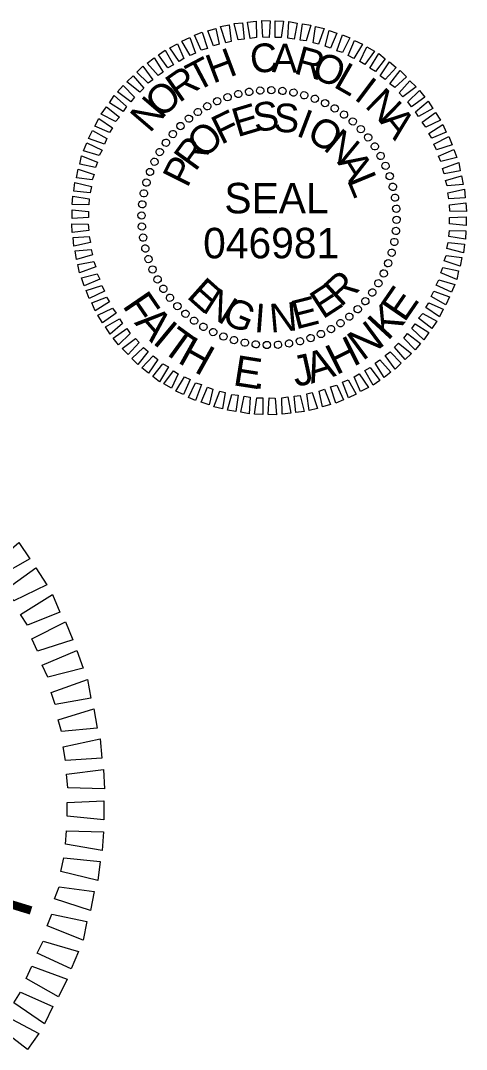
# Model space of a CAD drawing. Extents: x 1184048.9 to 1184122, y 1246638.9 to 1246660.6.
# Drawn here: x 1184120.43 to 1184122.001, y 1246653.225 to 1246656.855 of the extents above; entities that cross this region are included whole.
import ezdxf

# ---------------------------------------------------------------- set-up
doc = ezdxf.new("R2010")
doc.units = 0
doc.layers.add('Sheet PE Seal CELL', color=7, linetype='Continuous')

msp = doc.modelspace()

# ---------------------------------------------------------------- linework, layer by layer
at = {"layer": 'Sheet PE Seal CELL'}
for p, q in [((1184121.1588, 1246656.585), (1184121.1588, 1246656.585)), ((1184121.1964, 1246656.5958), (1184121.1964, 1246656.5958)), ((1184121.2359, 1246656.6029), (1184121.2359, 1246656.6029)), ((1184121.2744, 1246656.6083), (1184121.2744, 1246656.6083)), ((1184121.3138, 1246656.6092), (1184121.3138, 1246656.6092)), ((1184121.3532, 1246656.6065), (1184121.3532, 1246656.6065)), ((1184121.3917, 1246656.6003), (1184121.3917, 1246656.6003)), ((1184121.4293, 1246656.5922), (1184121.4293, 1246656.5922)), ((1184121.467, 1246656.5796), (1184121.467, 1246656.5796)), ((1184121.088, 1246656.5528), (1184121.088, 1246656.5528)), ((1184121.123, 1246656.5707), (1184121.123, 1246656.5707)), ((1184121.5028, 1246656.5635), (1184121.5028, 1246656.5635)), ((1184121.5377, 1246656.5456), (1184121.5377, 1246656.5456)), ((1184121.0227, 1246656.5098), (1184121.0227, 1246656.5098)), ((1184121.054, 1246656.5322), (1184121.054, 1246656.5322)), ((1184121.57, 1246656.5232), (1184121.57, 1246656.5232)), ((1184120.9931, 1246656.4829), (1184120.9931, 1246656.4829)), ((1184121.6013, 1246656.499), (1184121.6013, 1246656.499)), ((1184121.6291, 1246656.4722), (1184121.6291, 1246656.4722)), ((1184120.9662, 1246656.4551), (1184120.9662, 1246656.4551)), ((1184121.656, 1246656.4426), (1184121.656, 1246656.4426)), ((1184120.942, 1246656.4238), (1184120.942, 1246656.4238)), ((1184121.6784, 1246656.4112), (1184121.6784, 1246656.4112)), ((1184120.9196, 1246656.3915), (1184120.9196, 1246656.3915)), ((1184121.699, 1246656.3772), (1184121.699, 1246656.3772)), ((1184120.9017, 1246656.3566), (1184120.9017, 1246656.3566)), ((1184121.7169, 1246656.3423), (1184121.7169, 1246656.3423)), ((1184120.8856, 1246656.3208), (1184120.8856, 1246656.3208)), ((1184121.7312, 1246656.3064), (1184121.7312, 1246656.3064)), ((1184120.8731, 1246656.2831), (1184120.8731, 1246656.2831)), ((1184121.742, 1246656.2688), (1184121.742, 1246656.2688)), ((1184120.865, 1246656.2455), (1184120.865, 1246656.2455)), ((1184121.7491, 1246656.2294), (1184121.7491, 1246656.2294)), ((1184120.8587, 1246656.207), (1184120.8587, 1246656.207)), ((1184121.7545, 1246656.1909), (1184121.7545, 1246656.1909)), ((1184120.856, 1246656.1676), (1184120.856, 1246656.1676)), ((1184121.3057, 1246656.1595), (1184121.3057, 1246656.1595)), ((1184121.7554, 1246656.1515), (1184121.7554, 1246656.1515)), ((1184120.8569, 1246656.1282), (1184120.8569, 1246656.1282)), ((1184121.7527, 1246656.1121), (1184121.7527, 1246656.1121)), ((1184120.8623, 1246656.0897), (1184120.8623, 1246656.0897)), ((1184121.7464, 1246656.0735), (1184121.7464, 1246656.0735)), ((1184120.8695, 1246656.0502), (1184120.8695, 1246656.0502)), ((1184121.7384, 1246656.0359), (1184121.7384, 1246656.0359)), ((1184120.8802, 1246656.0126), (1184120.8802, 1246656.0126)), ((1184121.7258, 1246655.9983), (1184121.7258, 1246655.9983)), ((1184120.8946, 1246655.9768), (1184120.8946, 1246655.9768)), ((1184121.7097, 1246655.9625), (1184121.7097, 1246655.9625)), ((1184120.9125, 1246655.9419), (1184120.9125, 1246655.9419)), ((1184121.6918, 1246655.9275), (1184121.6918, 1246655.9275)), ((1184120.9331, 1246655.9078), (1184120.9331, 1246655.9078)), ((1184121.6694, 1246655.8953), (1184121.6694, 1246655.8953)), ((1184120.9555, 1246655.8765), (1184120.9555, 1246655.8765)), ((1184121.6452, 1246655.8639), (1184121.6452, 1246655.8639)), ((1184120.9823, 1246655.8469), (1184120.9823, 1246655.8469)), ((1184121.0101, 1246655.82), (1184121.0101, 1246655.82)), ((1184121.6183, 1246655.8362), (1184121.6183, 1246655.8362)), ((1184121.0415, 1246655.7958), (1184121.0415, 1246655.7958)), ((1184121.5574, 1246655.7869), (1184121.5574, 1246655.7869)), ((1184121.5888, 1246655.8093), (1184121.5888, 1246655.8093)), ((1184121.0737, 1246655.7735), (1184121.0737, 1246655.7735)), ((1184121.1087, 1246655.7555), (1184121.1087, 1246655.7555)), ((1184121.4885, 1246655.7484), (1184121.4885, 1246655.7484)), ((1184121.5234, 1246655.7663), (1184121.5234, 1246655.7663)), ((1184121.1445, 1246655.7394), (1184121.1445, 1246655.7394)), ((1184121.1821, 1246655.7269), (1184121.1821, 1246655.7269)), ((1184121.2197, 1246655.7188), (1184121.2197, 1246655.7188)), ((1184121.2582, 1246655.7125), (1184121.2582, 1246655.7125)), ((1184121.2977, 1246655.7099), (1184121.2977, 1246655.7099)), ((1184121.3371, 1246655.7107), (1184121.3371, 1246655.7107)), ((1184121.3756, 1246655.7161), (1184121.3756, 1246655.7161)), ((1184121.415, 1246655.7233), (1184121.415, 1246655.7233)), ((1184121.4526, 1246655.734), (1184121.4526, 1246655.734))]:
    msp.add_line(p, q, dxfattribs=at)
for points in [[(1184121.1534, 1246656.7767), (1184121.1346, 1246656.8332), (1184121.1651, 1246656.8394), (1184121.1723, 1246656.7812)], [(1184121.1964, 1246656.7866), (1184121.1821, 1246656.8439), (1184121.2117, 1246656.8466), (1184121.2179, 1246656.7893)], [(1184121.2394, 1246656.7919), (1184121.2296, 1246656.8493), (1184121.26, 1246656.8529), (1184121.2609, 1246656.7946)], [(1184121.2842, 1246656.7964), (1184121.2797, 1246656.8547), (1184121.3093, 1246656.8538), (1184121.3057, 1246656.7955)], [(1184121.3272, 1246656.7955), (1184121.3272, 1246656.8538), (1184121.3568, 1246656.8529), (1184121.3487, 1246656.7946)], [(1184121.372, 1246656.7928), (1184121.3756, 1246656.8511), (1184121.4052, 1246656.8457), (1184121.3935, 1246656.7893)], [(1184121.415, 1246656.7857), (1184121.4231, 1246656.843), (1184121.4526, 1246656.8385), (1184121.4365, 1246656.783)], [(1184121.4607, 1246656.7758), (1184121.4696, 1246656.834), (1184121.5001, 1246656.8269), (1184121.4795, 1246656.7713)], [(1184121.0666, 1246656.7507), (1184121.0433, 1246656.8027), (1184121.0701, 1246656.8134), (1184121.0889, 1246656.7561)], [(1184121.1104, 1246656.7651), (1184121.0898, 1246656.8188), (1184121.1176, 1246656.8269), (1184121.1293, 1246656.7713)], [(1184121.5037, 1246656.7642), (1184121.5171, 1246656.8197), (1184121.5449, 1246656.8108), (1184121.5225, 1246656.7579)], [(1184121.544, 1246656.7481), (1184121.5646, 1246656.8045), (1184121.5897, 1246656.7937), (1184121.5646, 1246656.7418)], [(1184120.9886, 1246656.7104), (1184120.9555, 1246656.7588), (1184120.9832, 1246656.7731), (1184121.0056, 1246656.7212)], [(1184121.0271, 1246656.7319), (1184120.9985, 1246656.7821), (1184121.0262, 1246656.7946), (1184121.0468, 1246656.74)], [(1184121.5843, 1246656.731), (1184121.6067, 1246656.7839), (1184121.6345, 1246656.7713), (1184121.604, 1246656.7212)], [(1184121.6255, 1246656.7104), (1184121.6497, 1246656.7615), (1184121.6766, 1246656.7463), (1184121.6425, 1246656.6997)], [(1184120.9492, 1246656.688), (1184120.9161, 1246656.7337), (1184120.9394, 1246656.7507), (1184120.9689, 1246656.6988)], [(1184121.6604, 1246656.6862), (1184121.6918, 1246656.7382), (1184121.7151, 1246656.7194), (1184121.6802, 1246656.6755)], [(1184120.8793, 1246656.6334), (1184120.8399, 1246656.6728), (1184120.8614, 1246656.6943), (1184120.8964, 1246656.6459)], [(1184120.9152, 1246656.6612), (1184120.8766, 1246656.7042), (1184120.9008, 1246656.723), (1184120.9322, 1246656.6728)], [(1184121.6972, 1246656.6594), (1184121.7303, 1246656.7086), (1184121.7536, 1246656.6889), (1184121.7142, 1246656.6468)], [(1184120.8498, 1246656.602), (1184120.8041, 1246656.6388), (1184120.8265, 1246656.6594), (1184120.8641, 1246656.6164)], [(1184121.7312, 1246656.6316), (1184121.7679, 1246656.6782), (1184121.7894, 1246656.6567), (1184121.7482, 1246656.6182)], [(1184120.8184, 1246656.568), (1184120.7718, 1246656.6029), (1184120.7915, 1246656.6262), (1184120.831, 1246656.5841)], [(1184121.7635, 1246656.6003), (1184121.802, 1246656.6424), (1184121.8235, 1246656.6209), (1184121.7769, 1246656.5859)], [(1184120.7915, 1246656.534), (1184120.7432, 1246656.5644), (1184120.7602, 1246656.5904), (1184120.8032, 1246656.551)], [(1184121.7948, 1246656.568), (1184121.836, 1246656.6083), (1184121.8548, 1246656.5841), (1184121.8074, 1246656.5501)], [(1184120.7647, 1246656.4981), (1184120.7145, 1246656.525), (1184120.7324, 1246656.5501), (1184120.779, 1246656.5143)], [(1184121.8217, 1246656.5331), (1184121.8656, 1246656.5707), (1184121.8826, 1246656.5447), (1184121.8324, 1246656.516)], [(1184120.7432, 1246656.4596), (1184120.6921, 1246656.482), (1184120.7056, 1246656.5098), (1184120.7539, 1246656.4766)], [(1184121.845, 1246656.4963), (1184121.8925, 1246656.5304), (1184121.9095, 1246656.5035), (1184121.8575, 1246656.4784)], [(1184121.8683, 1246656.4569), (1184121.9184, 1246656.4883), (1184121.9301, 1246656.4605), (1184121.879, 1246656.4399)], [(1184120.7253, 1246656.4184), (1184120.6697, 1246656.439), (1184120.6832, 1246656.4668), (1184120.7342, 1246656.4381)], [(1184121.8862, 1246656.4184), (1184121.939, 1246656.4453), (1184121.9507, 1246656.4166), (1184121.8951, 1246656.3987)], [(1184120.7073, 1246656.379), (1184120.6518, 1246656.3951), (1184120.6635, 1246656.4229), (1184120.7172, 1246656.3978)], [(1184121.9023, 1246656.3763), (1184121.9569, 1246656.3996), (1184121.9668, 1246656.3718), (1184121.9113, 1246656.3575)], [(1184120.6939, 1246656.336), (1184120.6384, 1246656.3476), (1184120.6446, 1246656.3772), (1184120.7011, 1246656.3548)], [(1184120.6823, 1246656.293), (1184120.6267, 1246656.3002), (1184120.633, 1246656.3306), (1184120.6894, 1246656.3118)], [(1184121.9166, 1246656.3333), (1184121.974, 1246656.3539), (1184121.9793, 1246656.3244), (1184121.9229, 1246656.3145)], [(1184121.9274, 1246656.2903), (1184121.9838, 1246656.3073), (1184121.9892, 1246656.2769), (1184121.9328, 1246656.2715)], [(1184120.6751, 1246656.2473), (1184120.6178, 1246656.2527), (1184120.6214, 1246656.2831), (1184120.6796, 1246656.2688)], [(1184121.9355, 1246656.2473), (1184121.9937, 1246656.2599), (1184121.9964, 1246656.2294), (1184121.939, 1246656.2258)], [(1184120.6706, 1246656.2043), (1184120.6124, 1246656.2061), (1184120.6142, 1246656.2357), (1184120.6724, 1246656.2258)], [(1184120.6697, 1246656.1595), (1184120.6115, 1246656.1568), (1184120.6115, 1246656.1873), (1184120.6697, 1246656.181)], [(1184121.9408, 1246656.2043), (1184121.9991, 1246656.2115), (1184122.0008, 1246656.181), (1184121.9426, 1246656.1828)], [(1184121.9417, 1246656.1595), (1184121.9999, 1246656.1622), (1184121.9999, 1246656.1318), (1184121.9417, 1246656.138)], [(1184120.6706, 1246656.1147), (1184120.6124, 1246656.1076), (1184120.6106, 1246656.138), (1184120.6688, 1246656.1362)], [(1184121.9408, 1246656.1147), (1184121.9991, 1246656.1129), (1184121.9973, 1246656.0834), (1184121.939, 1246656.0932)], [(1184120.676, 1246656.0717), (1184120.6178, 1246656.0592), (1184120.6151, 1246656.0897), (1184120.6724, 1246656.0932)], [(1184121.9363, 1246656.0717), (1184121.9937, 1246656.0664), (1184121.9901, 1246656.0359), (1184121.9319, 1246656.0502)], [(1184120.6841, 1246656.0287), (1184120.6276, 1246656.0117), (1184120.6222, 1246656.0422), (1184120.6787, 1246656.0476)], [(1184120.6948, 1246655.9857), (1184120.6375, 1246655.9651), (1184120.6321, 1246655.9947), (1184120.6885, 1246656.0046)], [(1184121.9292, 1246656.0261), (1184121.9847, 1246656.0189), (1184121.9784, 1246655.9884), (1184121.922, 1246656.0072)], [(1184120.7091, 1246655.9428), (1184120.6545, 1246655.9195), (1184120.6446, 1246655.9472), (1184120.7002, 1246655.9616)], [(1184121.9175, 1246655.9831), (1184121.9731, 1246655.9714), (1184121.9668, 1246655.9419), (1184121.9104, 1246655.9643)], [(1184121.9041, 1246655.9401), (1184121.9596, 1246655.9239), (1184121.948, 1246655.8962), (1184121.8942, 1246655.9213)], [(1184120.7253, 1246655.9007), (1184120.6724, 1246655.8738), (1184120.6608, 1246655.9024), (1184120.7163, 1246655.9204)], [(1184121.8862, 1246655.9007), (1184121.9417, 1246655.88), (1184121.9283, 1246655.8523), (1184121.8772, 1246655.8809)], [(1184120.7432, 1246655.8621), (1184120.693, 1246655.8308), (1184120.6814, 1246655.8585), (1184120.7324, 1246655.8792)], [(1184121.8683, 1246655.8594), (1184121.9193, 1246655.8371), (1184121.9059, 1246655.8093), (1184121.8575, 1246655.8424)], [(1184120.7665, 1246655.8227), (1184120.719, 1246655.7887), (1184120.702, 1246655.8156), (1184120.7539, 1246655.8406)], [(1184121.8468, 1246655.8209), (1184121.8969, 1246655.7941), (1184121.879, 1246655.769), (1184121.8324, 1246655.8048)], [(1184120.7898, 1246655.786), (1184120.7459, 1246655.7484), (1184120.7288, 1246655.7743), (1184120.779, 1246655.803)], [(1184121.8199, 1246655.7851), (1184121.8683, 1246655.7546), (1184121.8512, 1246655.7287), (1184121.8083, 1246655.7681)], [(1184120.8166, 1246655.7511), (1184120.7754, 1246655.7107), (1184120.7566, 1246655.7349), (1184120.8041, 1246655.769)], [(1184121.793, 1246655.7511), (1184121.8396, 1246655.7161), (1184121.8199, 1246655.6928), (1184121.7805, 1246655.7349)], [(1184120.848, 1246655.7188), (1184120.8095, 1246655.6767), (1184120.788, 1246655.6982), (1184120.8345, 1246655.7331)], [(1184121.7617, 1246655.717), (1184121.8074, 1246655.6803), (1184121.785, 1246655.6597), (1184121.7473, 1246655.7027)], [(1184120.8802, 1246655.6875), (1184120.8435, 1246655.6409), (1184120.822, 1246655.6624), (1184120.8632, 1246655.7009)], [(1184120.9143, 1246655.6597), (1184120.8811, 1246655.6104), (1184120.8578, 1246655.6301), (1184120.8972, 1246655.6722)], [(1184121.7321, 1246655.6857), (1184121.7715, 1246655.6463), (1184121.75, 1246655.6248), (1184121.7151, 1246655.6731)], [(1184120.951, 1246655.6328), (1184120.9196, 1246655.5809), (1184120.8964, 1246655.5997), (1184120.9313, 1246655.6436)], [(1184121.6963, 1246655.6579), (1184121.7348, 1246655.6149), (1184121.7106, 1246655.5961), (1184121.6793, 1246655.6463)], [(1184120.9859, 1246655.6086), (1184120.9617, 1246655.5576), (1184120.9349, 1246655.5728), (1184120.9689, 1246655.6194)], [(1184121.6228, 1246655.6086), (1184121.656, 1246655.5603), (1184121.6282, 1246655.5459), (1184121.6058, 1246655.5979)], [(1184121.6622, 1246655.631), (1184121.6954, 1246655.5853), (1184121.6721, 1246655.5683), (1184121.6425, 1246655.6203)], [(1184121.0271, 1246655.588), (1184121.0047, 1246655.5352), (1184120.977, 1246655.5477), (1184121.0074, 1246655.5979)], [(1184121.0674, 1246655.571), (1184121.0468, 1246655.5146), (1184121.0218, 1246655.5253), (1184121.0468, 1246655.5773)], [(1184121.5449, 1246655.5683), (1184121.5682, 1246655.5164), (1184121.5413, 1246655.5056), (1184121.5225, 1246655.5629)], [(1184121.5843, 1246655.5871), (1184121.613, 1246655.537), (1184121.5852, 1246655.5244), (1184121.5646, 1246655.5791)], [(1184121.1078, 1246655.5549), (1184121.0943, 1246655.4993), (1184121.0666, 1246655.5083), (1184121.0889, 1246655.5612)], [(1184121.1508, 1246655.5432), (1184121.1418, 1246655.485), (1184121.1113, 1246655.4922), (1184121.1319, 1246655.5477)], [(1184121.1964, 1246655.5334), (1184121.1884, 1246655.4761), (1184121.1588, 1246655.4805), (1184121.1749, 1246655.5361)], [(1184121.2394, 1246655.5262), (1184121.2359, 1246655.468), (1184121.2063, 1246655.4734), (1184121.2179, 1246655.5298)], [(1184121.372, 1246655.5271), (1184121.3819, 1246655.4698), (1184121.3514, 1246655.4662), (1184121.3505, 1246655.5244)], [(1184121.415, 1246655.5325), (1184121.4293, 1246655.4752), (1184121.3998, 1246655.4725), (1184121.3935, 1246655.5298)], [(1184121.458, 1246655.5423), (1184121.4768, 1246655.4859), (1184121.4464, 1246655.4796), (1184121.4392, 1246655.5379)], [(1184121.501, 1246655.554), (1184121.5216, 1246655.5002), (1184121.4938, 1246655.4922), (1184121.4822, 1246655.5477)], [(1184121.2842, 1246655.5235), (1184121.2842, 1246655.4653), (1184121.2547, 1246655.4662), (1184121.2627, 1246655.5244)], [(1184121.3272, 1246655.5226), (1184121.3317, 1246655.4644), (1184121.3021, 1246655.4653), (1184121.3057, 1246655.5235)], [(1184120.3263, 1246654.9301), (1184120.4243, 1246655.014), (1184120.4622, 1246654.9561), (1184120.3503, 1246654.8921)], [(1184120.3783, 1246654.8482), (1184120.4842, 1246654.9241), (1184120.5222, 1246654.8641), (1184120.4063, 1246654.8082)], [(1184120.4303, 1246654.7602), (1184120.5422, 1246654.8302), (1184120.5681, 1246654.7682), (1184120.4542, 1246654.7223)], [(1184120.4702, 1246654.6743), (1184120.5881, 1246654.7343), (1184120.6141, 1246654.6703), (1184120.4902, 1246654.6303)], [(1184120.5062, 1246654.5804), (1184120.6281, 1246654.6323), (1184120.6501, 1246654.5704), (1184120.5262, 1246654.5384)], [(1184120.5382, 1246654.4845), (1184120.6661, 1246654.5304), (1184120.6781, 1246654.4645), (1184120.5522, 1246654.4425)], [(1184120.5621, 1246654.3885), (1184120.688, 1246654.4265), (1184120.7, 1246654.3586), (1184120.5741, 1246654.3466)], [(1184120.5801, 1246654.2926), (1184120.71, 1246654.3206), (1184120.716, 1246654.2526), (1184120.5881, 1246654.2446)], [(1184120.5921, 1246654.1967), (1184120.722, 1246654.2127), (1184120.726, 1246654.1447), (1184120.5961, 1246654.1487)], [(1184120.5941, 1246654.0968), (1184120.724, 1246654.1028), (1184120.724, 1246654.0348), (1184120.5941, 1246654.0488)], [(1184120.5921, 1246653.9968), (1184120.722, 1246653.9928), (1184120.718, 1246653.9269), (1184120.5881, 1246653.9489)], [(1184120.5821, 1246653.9009), (1184120.71, 1246653.8889), (1184120.702, 1246653.821), (1184120.5721, 1246653.853)], [(1184120.5661, 1246653.799), (1184120.69, 1246653.783), (1184120.6761, 1246653.7151), (1184120.5502, 1246653.757)], [(1184120.5402, 1246653.7031), (1184120.6641, 1246653.6771), (1184120.6501, 1246653.6112), (1184120.5242, 1246653.6611)], [(1184120.5102, 1246653.6072), (1184120.6341, 1246653.5712), (1184120.6081, 1246653.5092), (1184120.4882, 1246653.5652)], [(1184120.4702, 1246653.5192), (1184120.5941, 1246653.4733), (1184120.5641, 1246653.4113), (1184120.4502, 1246653.4753)], [(1184120.4303, 1246653.4273), (1184120.5442, 1246653.3773), (1184120.5142, 1246653.3154), (1184120.4063, 1246653.3893)], [(1184120.3823, 1246653.3414), (1184120.4942, 1246653.2814), (1184120.4542, 1246653.2255), (1184120.3503, 1246653.3054)]]:
    msp.add_lwpolyline(points, close=True, dxfattribs=at)
for centre, major_axis in [((1184121.2354, 1246656.6033), (-0.002, 0.0127)), ((1184121.2744, 1246656.6078), (-0.0009, 0.0129)), ((1184121.3136, 1246656.6088), (0.0002, 0.0129)), ((1184121.3527, 1246656.6064), (0.0013, 0.0128)), ((1184121.3915, 1246656.6006), (0.0025, 0.0127)), ((1184121.123, 1246656.57), (-0.0052, 0.0118)), ((1184121.1594, 1246656.5844), (-0.0042, 0.0122)), ((1184121.197, 1246656.5955), (-0.0031, 0.0125)), ((1184121.4296, 1246656.5914), (0.0036, 0.0124)), ((1184121.4667, 1246656.579), (0.0046, 0.012)), ((1184121.0545, 1246656.532), (-0.0072, 0.0107)), ((1184121.0879, 1246656.5525), (-0.0063, 0.0113)), ((1184121.5027, 1246656.5634), (0.0057, 0.0116)), ((1184121.5371, 1246656.5447), (0.0066, 0.0111)), ((1184121.023, 1246656.5087), (-0.0081, 0.01)), ((1184121.5698, 1246656.523), (0.0076, 0.0104)), ((1184121.6005, 1246656.4986), (0.00846, 0.00974)), ((1184120.9936, 1246656.4827), (-0.00896, 0.00928)), ((1184121.6289, 1246656.4717), (0.00928, 0.00896)), ((1184120.9422, 1246656.4236), (-0.0104, 0.0076)), ((1184120.9666, 1246656.4543), (-0.00974, 0.00846)), ((1184121.6549, 1246656.4423), (0.01, 0.0081)), ((1184120.9206, 1246656.3909), (-0.0111, 0.0066)), ((1184121.6782, 1246656.4108), (0.0107, 0.0072)), ((1184120.9019, 1246656.3565), (-0.0116, 0.0057)), ((1184121.6987, 1246656.3774), (0.0113, 0.0063)), ((1184120.8862, 1246656.3206), (-0.012, 0.0046)), ((1184121.7162, 1246656.3423), (0.0118, 0.0052)), ((1184120.8738, 1246656.2834), (-0.0124, 0.0036)), ((1184121.7306, 1246656.3058), (0.0122, 0.0042)), ((1184120.8647, 1246656.2453), (-0.0127, 0.0025)), ((1184121.7417, 1246656.2682), (0.0125, 0.0031)), ((1184120.8589, 1246656.2065), (-0.0128, 0.0013)), ((1184121.7495, 1246656.2298), (0.0127, 0.002)), ((1184120.8565, 1246656.1674), (-0.0129, 0.0002)), ((1184121.7539, 1246656.1909), (0.0129, 0.0009)), ((1184121.755, 1246656.1517), (0.0129, -0.0002)), ((1184120.8575, 1246656.1282), (-0.0129, -0.0009)), ((1184121.7526, 1246656.1126), (0.0128, -0.0013)), ((1184120.8619, 1246656.0892), (-0.0127, -0.002)), ((1184121.7468, 1246656.0738), (0.0127, -0.0025)), ((1184120.8697, 1246656.0508), (-0.0125, -0.0031)), ((1184121.7376, 1246656.0357), (0.0124, -0.0036)), ((1184120.8809, 1246656.0132), (-0.0122, -0.0042)), ((1184121.7252, 1246655.9985), (0.012, -0.0046)), ((1184120.8952, 1246655.9768), (-0.0118, -0.0052)), ((1184121.7096, 1246655.9626), (0.0116, -0.0057)), ((1184120.9127, 1246655.9417), (-0.0113, -0.0063)), ((1184121.6909, 1246655.9281), (0.0111, -0.0066)), ((1184120.9332, 1246655.9083), (-0.0107, -0.0072)), ((1184120.9565, 1246655.8768), (-0.01, -0.0081)), ((1184121.6692, 1246655.8954), (0.0104, -0.0076)), ((1184120.9825, 1246655.8474), (-0.00928, -0.00896)), ((1184121.6448, 1246655.8647), (0.00974, -0.00846)), ((1184121.0109, 1246655.8204), (-0.00846, -0.00974)), ((1184121.5885, 1246655.8103), (0.0081, -0.01)), ((1184121.6178, 1246655.8363), (0.00896, -0.00928)), ((1184121.0416, 1246655.796), (-0.0076, -0.0104)), ((1184121.0743, 1246655.7744), (-0.0066, -0.0111)), ((1184121.5236, 1246655.7665), (0.0063, -0.0113)), ((1184121.557, 1246655.787), (0.0072, -0.0107)), ((1184121.1088, 1246655.7557), (-0.0057, -0.0116)), ((1184121.1447, 1246655.7401), (-0.0046, -0.012)), ((1184121.452, 1246655.7347), (0.0042, -0.0122)), ((1184121.4885, 1246655.7491), (0.0052, -0.0118)), ((1184121.1819, 1246655.7276), (-0.0036, -0.0124)), ((1184121.22, 1246655.7185), (-0.0025, -0.0127)), ((1184121.2588, 1246655.7127), (-0.0013, -0.0128)), ((1184121.2979, 1246655.7103), (-0.0002, -0.0129)), ((1184121.3371, 1246655.7113), (0.0009, -0.0129)), ((1184121.376, 1246655.7157), (0.002, -0.0127)), ((1184121.4144, 1246655.7236), (0.0031, -0.0125))]:
    msp.add_ellipse(centre, major_axis=major_axis, ratio=0.999708, dxfattribs=at)

# ---------------------------------------------------------------- texts
for s, height, rotation, p in [('C', 0.1011, 6.2199, (1184121.2439, 1246656.6674)), ('A', 0.101, 359.0203, (1184121.3147, 1246656.6728)), ('R', 0.1013, 344.6211, (1184121.3899, 1246656.6692)), ('T', 0.1018, 27.8198, (1184121.0495, 1246656.602)), ('H', 0.1015, 20.6195, (1184121.1078, 1246656.6316)), ('O', 0.1016, 337.4212, (1184121.4499, 1246656.6558)), ('L', 0.1019, 330.2209, (1184121.5288, 1246656.6226)), ('R', 0.102, 35.0205, (1184120.9886, 1246656.5626)), ('I', 0.1021, 323.0201, (1184121.6013, 1246656.5796)), ('O', 0.1021, 42.2217, (1184120.9268, 1246656.5071)), ('N', 0.1021, 315.8189, (1184121.6398, 1246656.5519)), ('N', 0.1021, 49.4235, (1184120.8856, 1246656.4551)), ('E', 0.1014, 16.6111, (1184121.1938, 1246656.4426)), ('S', 0.1011, 7.2556, (1184121.2556, 1246656.4614)), ('S', 0.101, 357.9004, (1184121.3201, 1246656.4623)), ('F', 0.1017, 25.967, (1184121.1364, 1246656.4157)), ('I', 0.1015, 339.1896, (1184121.3971, 1246656.4498)), ('O', 0.1019, 329.8335, (1184121.4329, 1246656.4372)), ('A', 0.1021, 308.6172, (1184121.6927, 1246656.499)), ('O', 0.1021, 44.6812, (1184121.0773, 1246656.3629)), ('N', 0.1021, 320.4766, (1184121.4929, 1246656.4014)), ('R', 0.102, 54.0397, (1184121.0459, 1246656.319)), ('P', 0.1017, 63.3989, (1184121.0173, 1246656.2616)), ('A', 0.1019, 301.7603, (1184121.544, 1246656.3548)), ('L', 0.1016, 292.4009, (1184121.5789, 1246656.293)), ('SEAL', 0.10746, 360, (1184121.1481, 1246656.1747)), ('R', 0.1021, 42.4814, (1184121.5583, 1246655.8415)), ('E', 0.1021, 318.2769, (1184121.0119, 1246655.8792)), ('E', 0.102, 33.1241, (1184121.4947, 1246655.7994)), ('F', 0.1085, 304.4142, (1184120.7867, 1246655.8488)), ('N', 0.102, 327.634, (1184121.0657, 1246655.8308)), ('E', 0.1085, 55.493, (1184121.7823, 1246655.787)), ('G', 0.1016, 336.9902, (1184121.1337, 1246655.7905)), ('I', 0.101, 355.7012, (1184121.2511, 1246655.7564)), ('N', 0.101, 5.0564, (1184121.3111, 1246655.7537)), ('E', 0.1013, 14.4118, (1184121.3998, 1246655.7645)), ('K', 0.1086, 47.2091, (1184121.7237, 1246655.7223)), ('A', 0.1086, 311.4309, (1184120.8286, 1246655.7877)), ('I', 0.1086, 320.2712, (1184120.8914, 1246655.7188)), ('N', 0.1086, 36.4833, (1184121.635, 1246655.6521)), ('T', 0.1086, 324.0731, (1184120.9215, 1246655.6923)), ('H', 0.1084, 330.8733, (1184120.9796, 1246655.6501)), ('H', 0.1083, 26.4993, (1184121.542, 1246655.6027)), ('E', 0.1076, 351.0577, (1184121.1754, 1246655.5689)), ('J', 0.1077, 12.4012, (1184121.3993, 1246655.5619)), ('A', 0.1079, 17.659, (1184121.4536, 1246655.573)), ('.', 0.1075, 358.167, (1184121.2495, 1246655.5573)), ('T', 0.2397, 72.9557, (1184120.4385, 1246653.6221))]:
    msp.add_text(s, height=height, rotation=rotation, dxfattribs=at).set_placement(p)
msp.add_text('046981', height=0.10746, dxfattribs=at).set_placement((1184121.0733, 1246656.0161))

doc.saveas('drawing.dxf')
